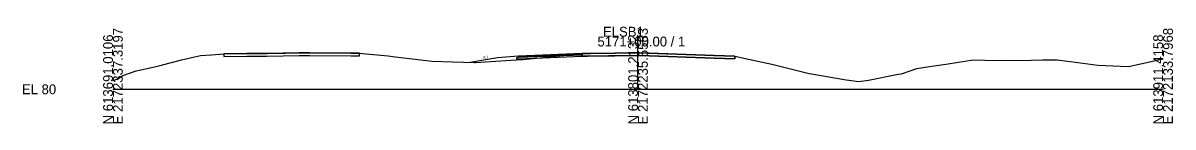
# Model space of a CAD drawing. Extents: x -26 to 1303, y -3010 to 12033.
# Drawn here: x -25.7 to 302.8, y -509.7 to -482.2 of the extents above; entities that cross this region are included whole.
import ezdxf

# ---------------------------------------------------------------- set-up
doc = ezdxf.new("R2010")
doc.units = 0
for name, color, linetype in [('RD_GPK_XS_Cell', 7, 'Continuous'), ('RD_XS_Base', 7, 'Continuous'), ('RD_XS_ExGround', 7, 'Continuous'), ('RD_XS_ExPaveRet', 7, 'Continuous'), ('RD_XS_Greenside', 7, 'Continuous'), ('RD_XS_Pave', 7, 'Continuous'), ('RD_XS_PaveOvlay_CP', 7, 'Continuous'), ('RD_XS_TieSlope', 7, 'Continuous'), ('RD_XS_TX_Slope', 7, 'Continuous')]:
    doc.layers.add(name, color=color, linetype=linetype)

msp = doc.modelspace()

# ---------------------------------------------------------------- linework, layer by layer
at = {"layer": 'RD_GPK_XS_Cell'}
for p, q in [((150, -500), (150, -485)), ((0, -500), (150, -500)), ((150, -500), (300, -500))]:
    msp.add_line(p, q, dxfattribs=at)
at = {"layer": 'RD_XS_Base'}
for p, q in [((115.39, -490.91), (115.89, -490.89)), ((115.39, -491.41), (115.39, -490.91)), ((115.39, -490.91), (115.39, -490.91)), ((115.89, -491.39), (115.39, -491.41)), ((115.39, -491.41), (115.39, -491.41)), ((115.39, -491.41), (115.39, -491.41)), ((115.89, -490.89), (134.01, -490.17)), ((134.01, -490.67), (115.89, -491.39)), ((115.89, -490.89), (115.89, -490.89)), ((115.89, -491.39), (115.89, -491.39)), ((134.01, -490.6), (134.01, -490.67))]:
    msp.add_line(p, q, dxfattribs=at)
at = {"layer": 'RD_XS_ExGround'}
msp.add_lwpolyline([(0, -497.53), (1.37, -497.06), (2.81, -496.04), (6.62, -494.75), (10.63, -493.86), (13.09, -493.29), (19.58, -491.61), (25.01, -490.34), (28.13, -490.22), (31.67, -489.93), (38.23, -489.85), (41.37, -489.81), (44.1, -489.77), (54.51, -489.61), (67.97, -489.72), (70.4, -489.74), (71.33, -489.81), (78.6, -490.49), (80.59, -490.73), (91.22, -491.94), (96.99, -492.21), (103.25, -492.4), (103.53, -492.41), (113.66, -491.71), (117.16, -491.49), (129.46, -490.29), (131.53, -490.09), (132.86, -489.96), (134.01, -489.85), (135.12, -489.83), (136.42, -489.81), (143.48, -489.71), (150.35, -489.62), (171.77, -490.37), (177.62, -490.61), (181.6, -491.4), (188.26, -492.81), (192.38, -493.87), (198.86, -495.48), (198.92, -495.49), (198.98, -495.51), (209.49, -497.31), (213.09, -497.78), (215.89, -497.36), (224.36, -495.71), (225.29, -495.55), (225.53, -495.5), (227.72, -494.74), (229.68, -494.09), (233.26, -493.52), (238.61, -492.7), (245.76, -491.61), (252.4, -491.75), (254.31, -491.74), (259.08, -491.75), (265.6, -491.62), (269.77, -491.6), (275.65, -492.4), (281.41, -493.14), (287.86, -493.42), (290.13, -493.5), (300, -491.3)], dxfattribs=at)
at = {"layer": 'RD_XS_ExPaveRet'}
for p, q in [((67.97, -489.72), (56.2, -489.62)), ((70.4, -489.74), (67.97, -489.72)), ((70.4, -489.74), (70.4, -489.74)), ((150.35, -489.62), (150.28, -489.62)), ((150.28, -489.62), (150.28, -489.62)), ((150.57, -489.62), (150.35, -489.62)), ((171.77, -490.37), (150.57, -489.62)), ((177.62, -490.61), (177.62, -490.61))]:
    msp.add_line(p, q, dxfattribs=at)
for points in [[(67.97, -489.72), (56.2, -489.62), (54.51, -489.61), (53.21, -489.63), (44.1, -489.77), (42.01, -489.8), (41.37, -489.81), (40.64, -489.82), (38.23, -489.85), (31.67, -489.93), (31.67, -489.93), (31.67, -489.93), (31.67, -490.48), (31.67, -490.68), (31.67, -490.68), (31.67, -490.68), (38.23, -490.6), (40.64, -490.57), (41.37, -490.56), (42.01, -490.55), (44.1, -490.52), (53.21, -490.38), (54.51, -490.36), (56.2, -490.37), (67.97, -490.47), (70.4, -490.49), (70.4, -490.49), (70.4, -489.93), (70.4, -489.74), (70.4, -489.74), (67.97, -489.72)], [(31.67, -489.93), (31.67, -489.93), (31.67, -490.48), (31.67, -490.68), (31.67, -490.68), (38.23, -490.6), (40.64, -490.57), (41.37, -490.56), (42.01, -490.55), (44.1, -490.52), (53.21, -490.38), (54.51, -490.36), (56.2, -490.37), (67.97, -490.47), (70.4, -490.49), (70.4, -490.49), (70.4, -489.93), (70.4, -489.74)], [(41.37, -489.81), (40.64, -489.82), (38.23, -489.85), (38.23, -489.85), (31.67, -489.93)], [(53.21, -489.63), (44.1, -489.77), (42.01, -489.8), (41.37, -489.81)], [(56.2, -489.62), (54.51, -489.61), (53.21, -489.63)], [(177.62, -490.61), (177.62, -491.2), (177.62, -491.36), (177.62, -491.36), (177.62, -491.36), (177.62, -491.36), (171.77, -491.12), (150.57, -490.37), (150.35, -490.37), (150.28, -490.37), (150.21, -490.37), (143.41, -490.46), (141.58, -490.49), (135.57, -490.58), (134.01, -490.6), (134.01, -490.01), (134.01, -489.85), (135.57, -489.83), (141.58, -489.74), (143.41, -489.71), (150.21, -489.62), (150.28, -489.62), (150.35, -489.62), (150.57, -489.62), (171.77, -490.37), (177.62, -490.61), (177.62, -490.61), (177.62, -490.61), (177.62, -490.61)], [(144.63, -489.7), (143.48, -489.71), (143.41, -489.71), (136.42, -489.81), (135.12, -489.83), (134.01, -489.85)], [(134.01, -489.85), (134.01, -490.01), (134.01, -490.6), (135.57, -490.58), (141.58, -490.49), (143.41, -490.46), (150.21, -490.37), (150.28, -490.37), (150.35, -490.37), (150.57, -490.37), (171.77, -491.12), (177.62, -491.36), (177.62, -491.36), (177.62, -491.36), (177.62, -491.2), (177.62, -490.61)], [(150.28, -489.62), (150.21, -489.62), (144.63, -489.7)], [(177.62, -490.61), (177.62, -490.61), (171.77, -490.37)]]:
    msp.add_lwpolyline(points, dxfattribs=at)
at = {"layer": 'RD_XS_Greenside'}
msp.add_line((109.89, -491.05), (102.02, -492.36), dxfattribs=at)
at = {"layer": 'RD_XS_Pave'}
for p, q in [((134.01, -489.85), (115.89, -490.57)), ((134.01, -490.01), (115.89, -490.73)), ((115.89, -490.73), (134.01, -490.01)), ((115.89, -490.89), (134.01, -490.17)), ((115.89, -490.57), (115.89, -490.57)), ((115.89, -490.57), (115.89, -490.73)), ((115.89, -490.73), (115.89, -490.73)), ((115.89, -490.73), (115.89, -490.89)), ((115.89, -490.73), (115.89, -490.73)), ((115.89, -490.73), (115.89, -490.73)), ((115.89, -490.89), (115.89, -490.89)), ((115.89, -490.89), (115.89, -490.89))]:
    msp.add_line(p, q, dxfattribs=at)
at = {"layer": 'RD_XS_PaveOvlay_CP'}
for p in [(134.01, -489.85), (115.89, -490.57)]:
    msp.add_line(p, (115.89, -490.57), dxfattribs=at)
at = {"layer": 'RD_XS_TieSlope'}
msp.add_line((115.89, -490.57), (109.89, -491.05), dxfattribs=at)

# ---------------------------------------------------------------- texts
at = {"layer": 'RD_GPK_XS_Cell'}
for s, p in [('E 2172337.3197', (2.8, -510)), ('E 2172235.5583', (152.8, -510)), ('E 2172133.7968', (302.8, -510)), ('N 613691.0106', (0, -510)), ('N 613801.2132', (150, -510)), ('N 613911.4158', (300, -510))]:
    msp.add_text(s, height=2.8, rotation=90, dxfattribs=at).set_placement(p)
for s, p in [('ELSB1', (140, -485)), ('5171+00.00 / 1', (138.42, -487.8)), ('EL 80', (-26, -501.4))]:
    msp.add_text(s, height=2.8, dxfattribs=at).set_placement(p)
at = {"layer": 'RD_XS_TX_Slope'}
msp.add_text('6:1', height=0.75, rotation=9.4642, dxfattribs=at).set_placement((105.86, -491.35))

doc.saveas('drawing.dxf')
